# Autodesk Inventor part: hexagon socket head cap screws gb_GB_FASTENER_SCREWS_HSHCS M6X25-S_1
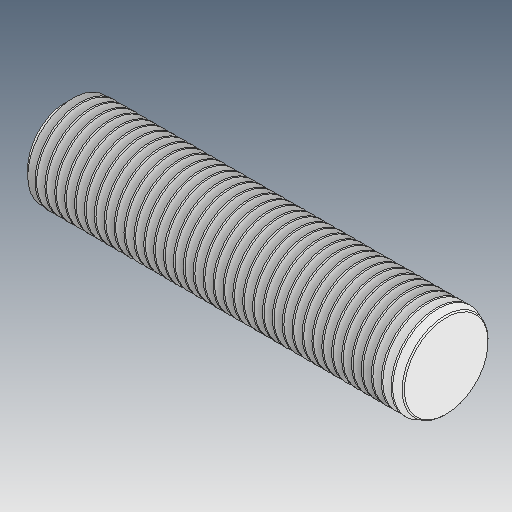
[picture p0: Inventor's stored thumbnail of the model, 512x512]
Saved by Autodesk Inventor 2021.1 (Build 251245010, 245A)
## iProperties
Created: 2021-05
Part Number: hexagon socket head cap screws gb_GB_FASTENER_SCREWS_HSHCS M6X25-S_1
Material: Ogólny
Document SubType Name: Modeling
Designer: user
Density: 1 g/cm^3
Appearance: Domyślna
Author: user
Revision Number: ÈÎºÎ
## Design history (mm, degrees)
feature "ÊäÈë1"
node "Bryła1"
